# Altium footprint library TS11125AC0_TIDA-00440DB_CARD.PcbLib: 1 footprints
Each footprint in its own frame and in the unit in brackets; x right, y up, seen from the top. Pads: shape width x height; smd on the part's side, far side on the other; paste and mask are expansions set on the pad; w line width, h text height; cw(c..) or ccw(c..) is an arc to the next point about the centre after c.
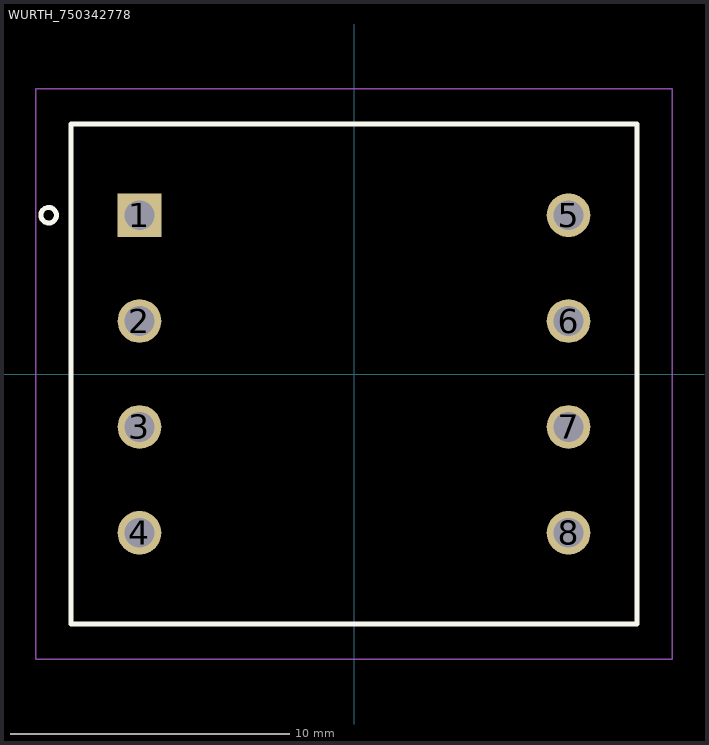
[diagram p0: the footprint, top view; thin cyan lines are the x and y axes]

## WURTH_750342778 [mm] "TRANSFORMER, 8PINS, THRU"
height 14.2
pads (8):
  rect 1.57x1.57 / inner round 1.57 / far side rect 1.57x1.57 hole 1.07: 1(-7.7,5.7)
  round 1.57 hole 1.07: 2(-7.7,1.9) 3(-7.7,-1.9) 4(-7.7,-5.7) 5(7.7,5.7) 6(7.7,1.9) 7(7.7,-1.9) 8(7.7,-5.7)
Top Overlay:
  circle w0.178: c-10.959,5.7 r0.279
  lines w0.178: -10.15,-8.975 10.15,-8.975 10.15,8.975 -10.15,8.975 -10.15,-8.975
  text ".Designator" at -1.524,10.668 h1.02
Bottom Overlay:
  lines w0.178: -10.164,-8.305 -10.164,-7.163 ; -10.164,-6.629 -10.164,-5.487 ; -10.164,-4.851 -10.164,-3.709 ; -10.164,-3.2 -10.164,-2.058 ; -10.164,-1.524 -10.164,-0.382 ; -10.164,0.254 -10.164,1.396 ; -10.164,1.905 -10.164,3.047 ; -10.15,3.556 -10.15,4.698 ; -10.15,5.207 -10.15,6.349 ; -10.15,6.883 -10.15,8.025 ; -9.09,-8.975 -7.948,-8.975 ; -9.09,8.975 -7.948,8.975 ; -7.185,-8.975 -6.043,-8.975 ; -7.185,8.975 -6.043,8.975 ; -5.28,-8.975 -4.138,-8.975 ; -5.28,8.975 -4.138,8.975 ; -3.429,-8.975 -2.287,-8.975 ; -3.429,8.975 -2.287,8.975 ; -1.778,-8.975 -0.636,-8.975 ; -1.778,8.975 -0.636,8.975 ; 0,-8.975 1.142,-8.975 ; 0,8.975 1.142,8.975 ; 1.905,-8.975 3.047,-8.975 ; 1.905,8.975 3.047,8.975 ; 3.81,-8.975 4.952,-8.975 ; 3.81,8.975 4.952,8.975 ; 5.715,-8.975 6.857,-8.975 ; 5.715,8.975 6.857,8.975 ; 7.62,-8.975 8.762,-8.975 ; 7.62,8.975 8.762,8.975 ; 10.136,-6.629 10.136,-5.487 ; 10.136,-4.851 10.136,-3.709 ; 10.136,-3.2 10.136,-2.058 ; 10.136,-1.524 10.136,-0.382 ; 10.136,0.254 10.136,1.396 ; 10.136,1.905 10.136,3.047 ; 10.15,3.556 10.15,4.698 ; 10.15,5.207 10.15,6.349 ; 10.15,6.883 10.15,8.025
Mechanical 5:
  circle w0.127: c-10.959,5.7 r0.279
  lines w0.127: -10.15,-8.975 -10.15,8.975 10.15,8.975 10.15,-8.975 -10.15,-8.975
  text "PRELIMINARY" at -5.08,-6.35 h1.52
  text ".Designator" at -1.524,-0.508 h1.02
Mechanical 15:
  lines w0.05: -11.42,-10.245 11.42,-10.245 11.42,10.245 -11.42,10.245 -11.42,-10.245
Mechanical 17:
  text "LEAD LENGTH: 3.5MM" at -8.128,-10.287 h1
3D body: height 14.3, standoff 0, extent -10.15,-8.975 10.15,8.975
